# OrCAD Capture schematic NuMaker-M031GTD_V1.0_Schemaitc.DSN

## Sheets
1 Nu-Link2-Me: size A3; title: Nu-Link2-Me; rev: 1.0; company: WHChiu; note: Nu-Link2-Me
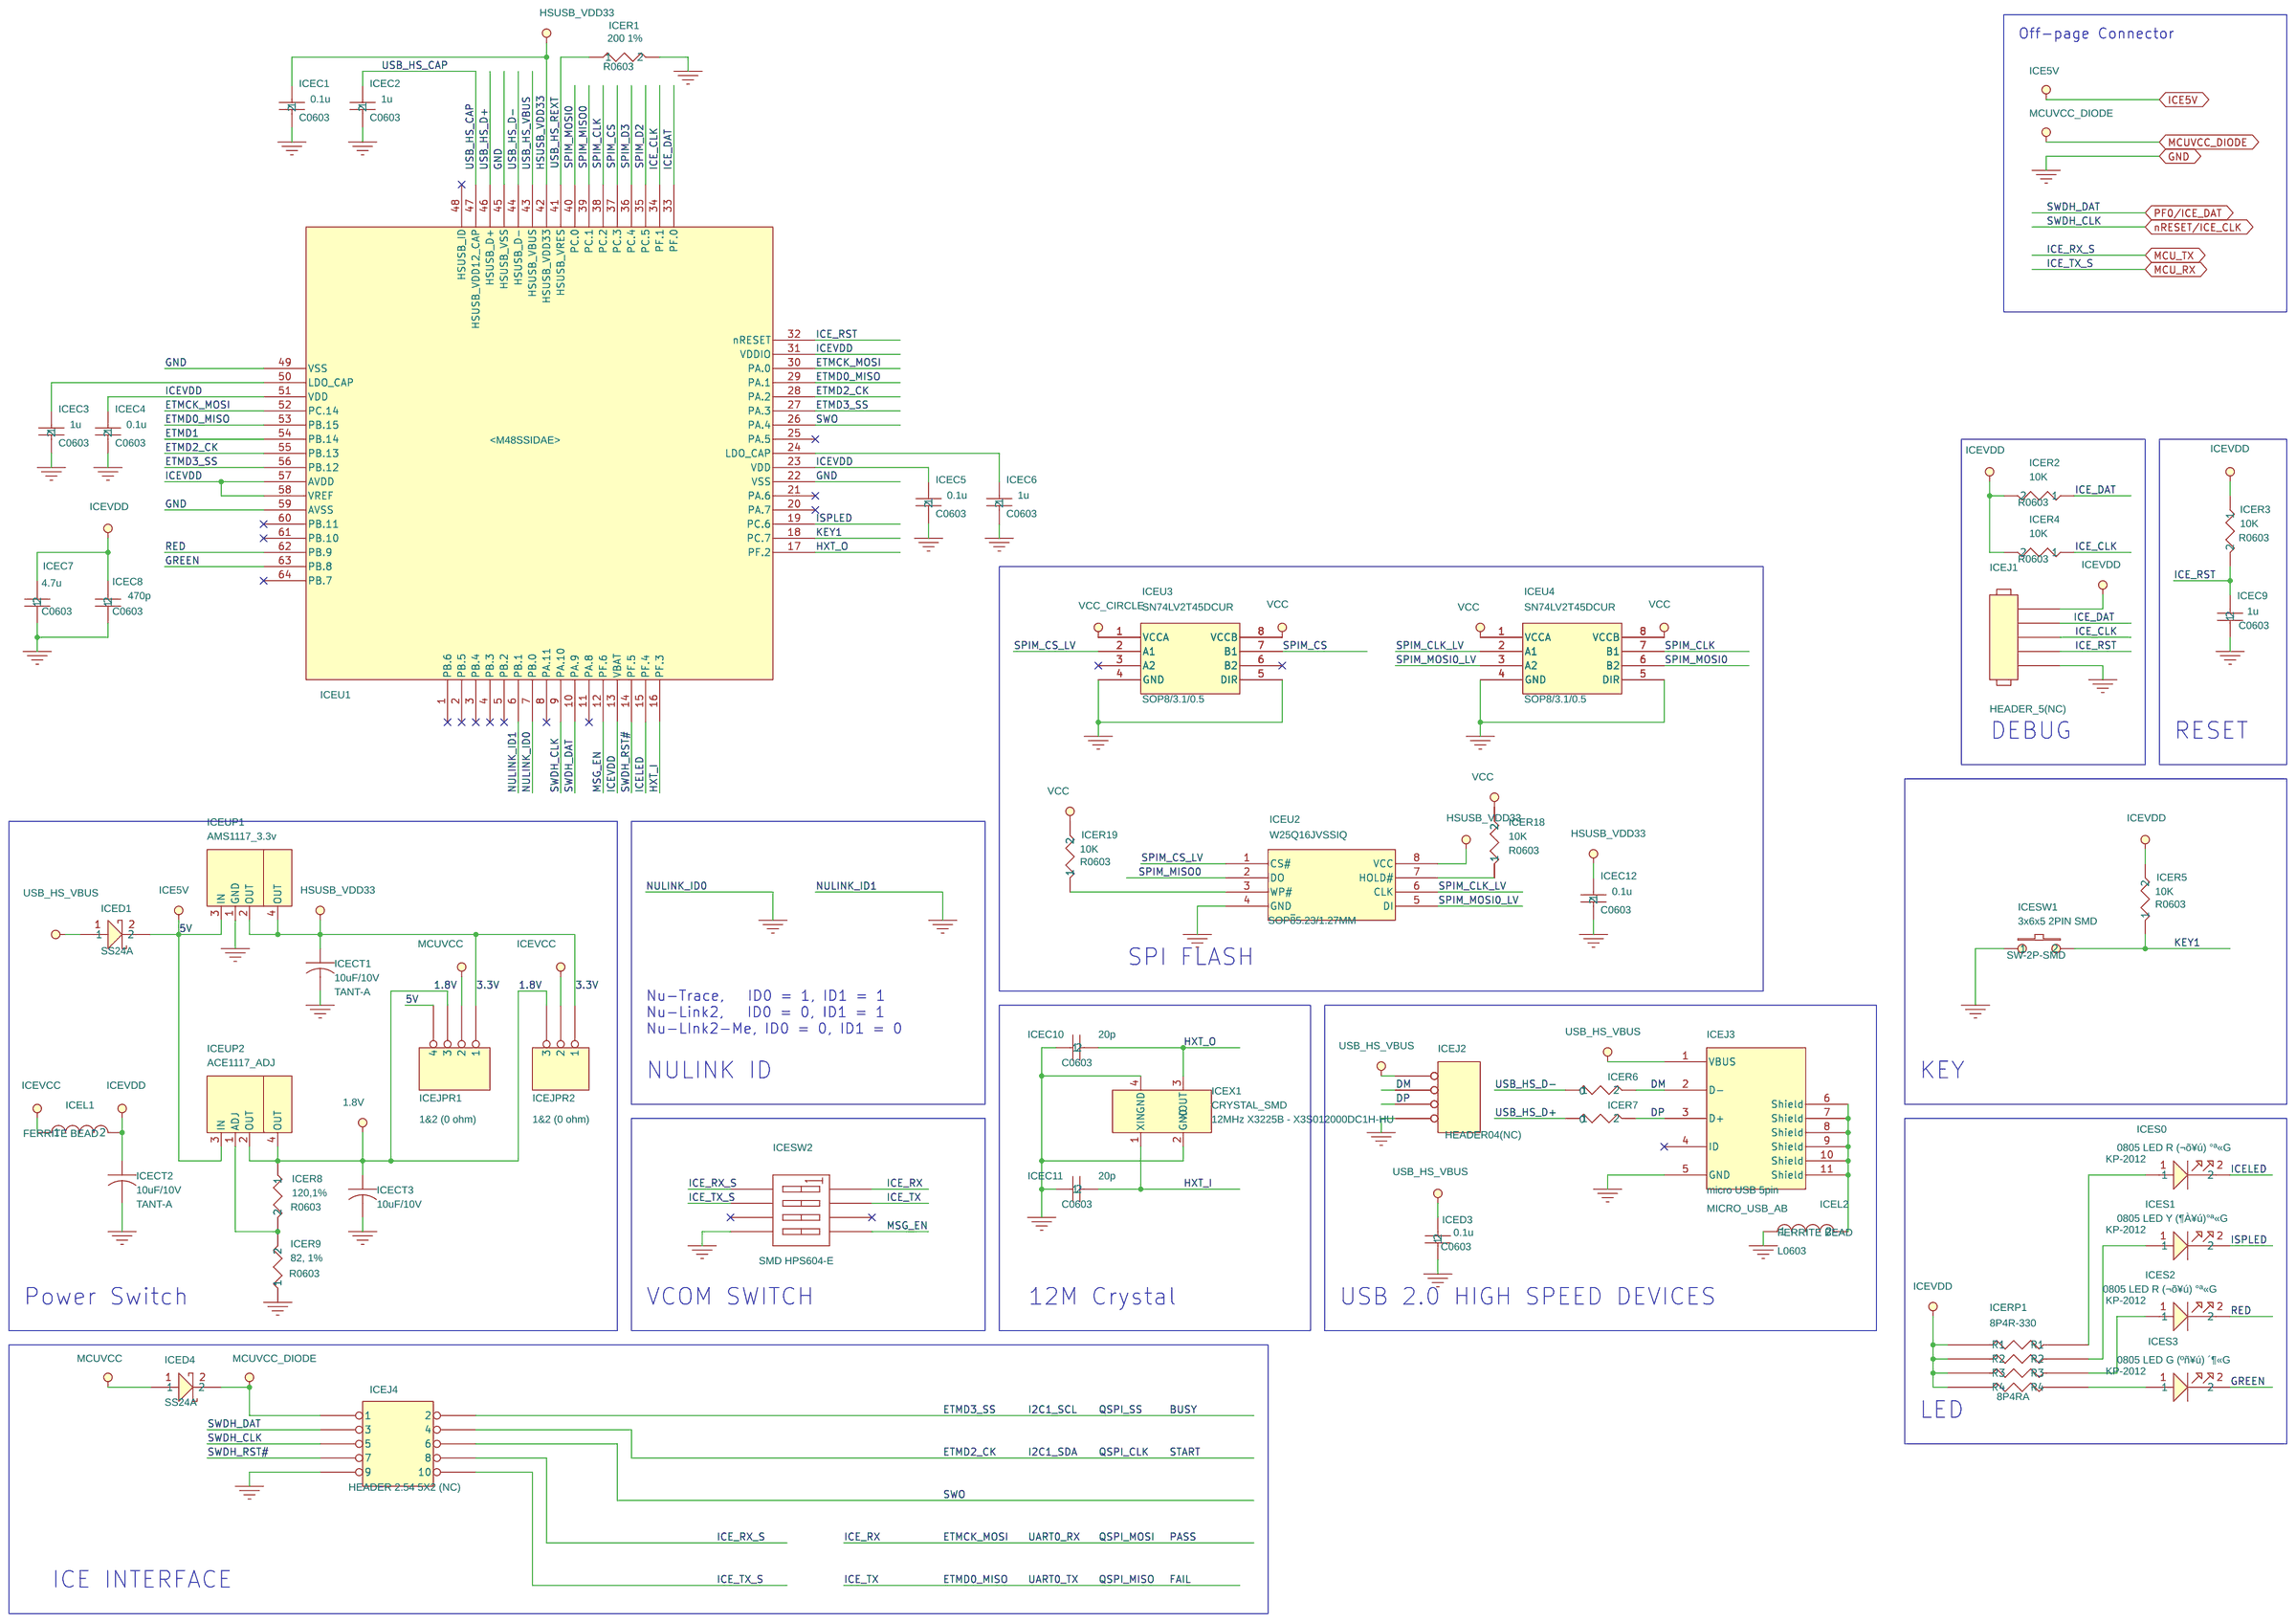
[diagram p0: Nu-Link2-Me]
2 M031G: size B; title: M031GTD2AE; rev: v1.1; note: NuMaker-M031G
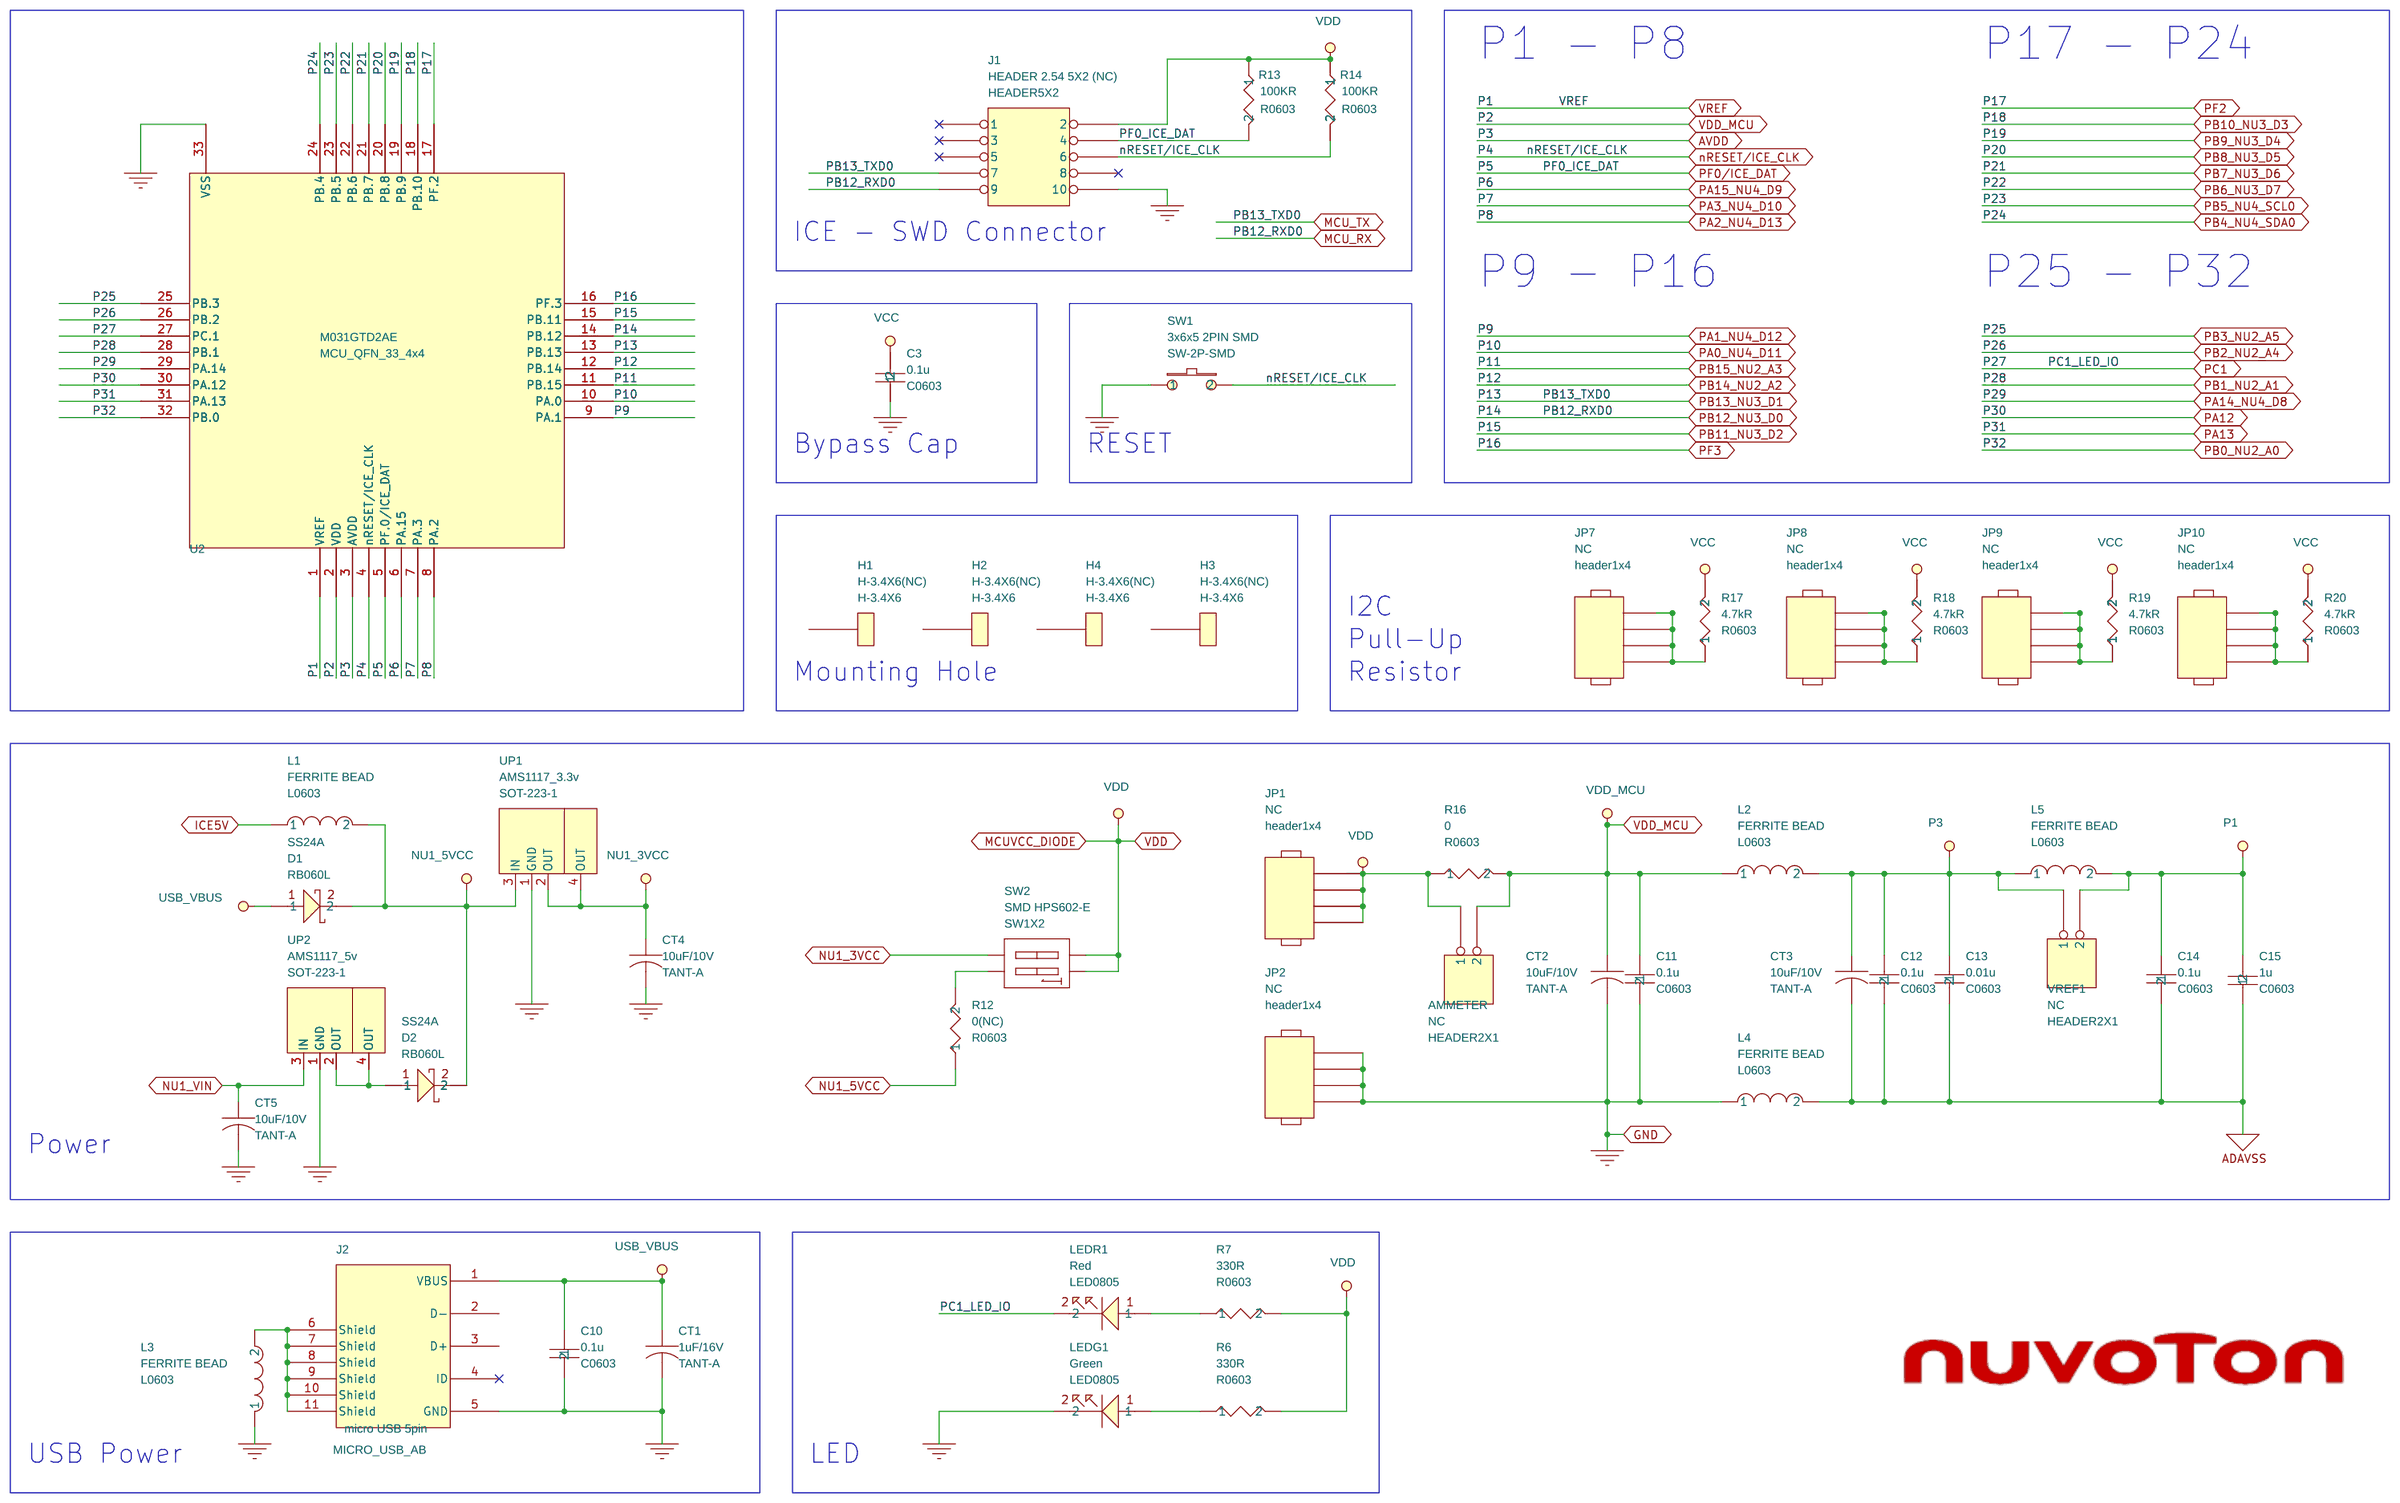
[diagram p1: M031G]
3 Ext. Connector: size A; title: Ext. Connector; rev: v1.1; note: NuMaker-M031G
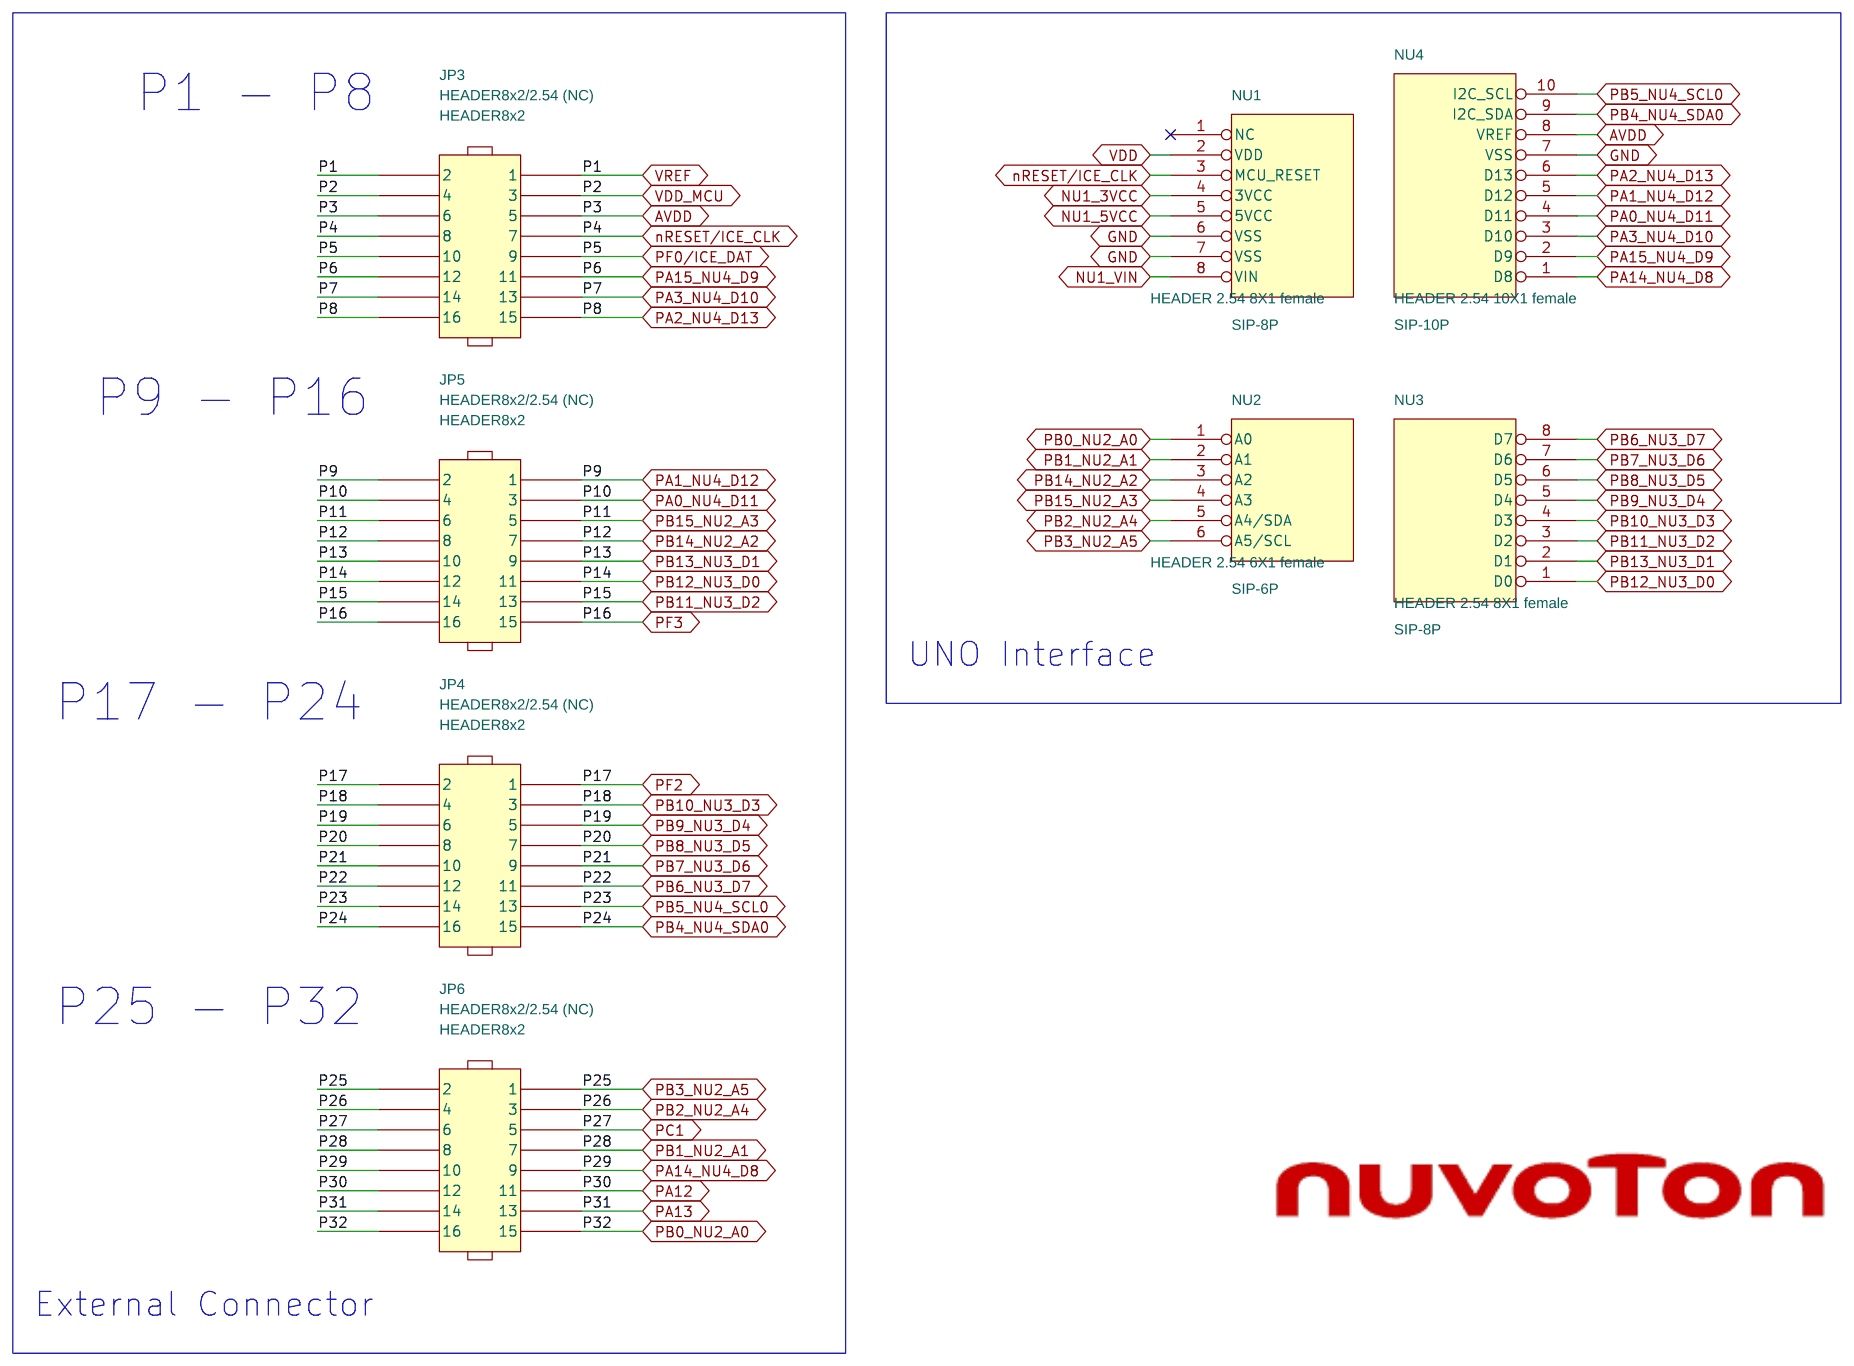
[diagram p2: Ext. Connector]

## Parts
sheet Ext. Connector
JP3  HEADER8x2/2.54 (NC)  [HEADER8x2]
JP4  HEADER8x2/2.54 (NC)  [HEADER8x2]
JP5  HEADER8x2/2.54 (NC)  [HEADER8x2]
JP6  HEADER8x2/2.54 (NC)  [HEADER8x2]
NU1  HEADER 2.54 8X1 female  [SIP-8P]
NU2  HEADER 2.54 6X1 female  [SIP-6P]
NU3  HEADER 2.54 8X1 female  [SIP-8P]
NU4  HEADER 2.54 10X1 female  [SIP-10P]
sheet M031G
AMMETER  NC  [HEADER2X1]
C3  0.1u  [C0603]
C10  0.1u  [C0603]
C11  0.1u  [C0603]
C12  0.1u  [C0603]
C13  0.01u  [C0603]
C14  0.1u  [C0603]
C15  1u  [C0603]
CT1  1uF/16V  [TANT-A]
CT2  10uF/10V  [TANT-A]
CT3  10uF/10V  [TANT-A]
CT4  10uF/10V  [TANT-A]
CT5  10uF/10V  [TANT-A]
D1  SS24A  [RB060L]
D2  SS24A  [RB060L]
H1  H-3.4X6(NC)  [H-3.4X6]
H2  H-3.4X6(NC)  [H-3.4X6]
H3  H-3.4X6(NC)  [H-3.4X6]
H4  H-3.4X6(NC)  [H-3.4X6]
J1  HEADER 2.54 5X2 (NC)  [HEADER5X2]
J2  micro USB 5pin  [MICRO_USB_AB]
JP1  NC  [header1x4]
JP2  NC  [header1x4]
JP7  NC  [header1x4]
JP8  NC  [header1x4]
JP9  NC  [header1x4]
JP10  NC  [header1x4]
L1  FERRITE BEAD  [L0603]
L2  FERRITE BEAD  [L0603]
L3  FERRITE BEAD  [L0603]
L4  FERRITE BEAD  [L0603]
L5  FERRITE BEAD  [L0603]
LEDG1  Green  [LED0805]
LEDR1  Red  [LED0805]
R6  330R  [R0603]
R7  330R  [R0603]
R12  0(NC)  [R0603]
R13  100KR  [R0603]
R14  100KR  [R0603]
R16  0  [R0603]
R17  4.7kR  [R0603]
R18  4.7kR  [R0603]
R19  4.7kR  [R0603]
R20  4.7kR  [R0603]
SW1  3x6x5 2PIN SMD  [SW-2P-SMD]
SW2  SMD HPS602-E  [SW1X2]
U2  M031TC1AE  [MCU_QFN_33_4x4]
UP1  AMS1117_3.3v  [SOT-223-1]
UP2  AMS1117_5v  [SOT-223-1]
VREF1  NC  [HEADER2X1]
sheet Nu-Link2-Me
ICEC1  0.1u  [C0603]
ICEC2  1u  [C0603]
ICEC3  1u  [C0603]
ICEC4  0.1u  [C0603]
ICEC5  0.1u  [C0603]
ICEC6  1u  [C0603]
ICEC7  4.7u  [C0603]
ICEC8  470p  [C0603]
ICEC9  1u  [C0603]
ICEC10  20p  [C0603]
ICEC11  20p  [C0603]
ICEC12  0.1u  [C0603]
ICECT1  10uF/10V  [TANT-A]
ICECT2  10uF/10V  [TANT-A]
ICECT3  10uF/10V  [TANT-A]
ICED1  SS24A  [RB060L]
ICED3  0.1u  [C0603]
ICED4  SS24A  [RB060L]
ICEJ1  HEADER_5(NC)  [HEADER5X1]
ICEJ2  HEADER04(NC)  [HEADER04]
ICEJ3  micro USB 5pin  [MICRO_USB_AB]
ICEJ4  HEADER 2.54 5X2 (NC)  [HEADER5X2]
ICEJPR1  1&2 (0 ohm)  [R0603X3]
ICEJPR2  1&2 (0 ohm)  [R0603X2]
ICEL1  FERRITE BEAD  [L0603]
ICEL2  FERRITE BEAD  [L0603]
ICER1  200 1%  [R0603]
ICER2  10K  [R0603]
ICER3  10K  [R0603]
ICER4  10K  [R0603]
ICER5  10K  [R0603]
ICER6  0  [R0603]
ICER7  0  [R0603]
ICER8  120,1%  [R0603]
ICER9  82, 1%  [R0603]
ICER18  10K  [R0603]
ICER19  10K  [R0603]
ICERP1  8P4R-330  [8P4RA]
ICES0  0805 LED R (¬õ¥ú) °ª«G  [KP-2012]
ICES1  0805 LED Y (¶À¥ú)°ª«G  [KP-2012]
ICES2  0805 LED R (¬õ¥ú) °ª«G  [KP-2012]
ICES3  0805 LED G (ºñ¥ú) ´¶«G  [KP-2012]
ICESW1  3x6x5 2PIN SMD  [SW-2P-SMD]
ICESW2  SMD HPS604-E  [SW1X4]
ICEU1  M48SSIDAE  [LQFP64_7x7_M48SSIDAE]
ICEU2  W25Q16JVSSIQ  [SOP8\5.23/1.27MM]
ICEU3  SN74LV2T45DCUR  [SOP8/3.1/0.5]
ICEU4  SN74LV2T45DCUR  [SOP8/3.1/0.5]
ICEUP1  AMS1117_3.3v  [SOT-223-1]
ICEUP2  ACE1117_ADJ  [SOT-223-1]
ICEX1  12MHz X3225B - X3S012000DC1H-HU  [CRYSTAL_SMD]

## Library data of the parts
JP3 = HEADER_8X2_3
JP4 = HEADER_8X2_1
JP5 = HEADER_8X2
JP6 = HEADER_8X2_2
NU1 = POWER_CONNECT_0
NU2 = ADC_CONNECT_0
NU3 = PWM0_CONNECT_0
NU4 = PWM1_CONNECT_1
AMMETER = HEADER_2_1
C3 ICED3 = CAP-C_1: Package: 0603; element_no: C0004
C10 = C_0.1u_3: element_no: C0004
C11 = C_0.1u: element_no: C0004
C12 = C_0.1u_1: element_no: C0004
C13 = C_0.1u_4: element_no: C0003
C14 = C_0.1u_2: element_no: C0004
C15 = CAP-C: Package: 0603; element_no: C0006
CT1 = C_1uF_16V
CT2-CT5 ICECT1-ICECT3 = C_10uF_10V
D1 ICED1 = D_SS24A
D2 ICED4 = D_SS24A_1
H1-H4 = TEST_POINT
ICEJ4 J1 = HEADER_5X2
ICEJ3 J2 = micro_USB_5pin_0
JP1 JP2 JP7-JP10 = HEADER_4
L1 = FERRITE_BEAD_4
L2 = FERRITE_BEAD_2
L3 = FERRITE_BEAD_3
ICEL2 L4 = FERRITE_BEAD_1
ICEL1 L5 = FERRITE_BEAD
LEDG1 = LED_0_1: Package: KP-2012; Vendor: Kingbright
LEDR1 = LED_0: Package: KP-2012; Vendor: Kingbright
ICER18 R6 = R_0_6: Package: 0603
ICER2 R7 = R_0: Package: 0603
R12 = R_0_5
ICER3 R13 = R_0_4: Package: 0603
ICER4 R14 = R_0_7: Package: 0603
R16 = R_0_9
R17 = R_0_1
R18 = R_0_2
R19 = R_0_3
R20 = R_0_8
ICESW1 SW1 = SW_PUSHBUTTON_0
SW2 = SW_DIP-4_2
U2 = M031TC1AE_1: M031TC1AE: M031GTD2AE
ICEUP1 UP1 UP2 = TO-247_Regulator_10
VREF1 = HEADER_2
ICEC1 = CAP-C_9: Package: 0603; element_no: C0004
ICEC2 = CAP-C_10: Package: 0603; element_no: C0006
ICEC3 = CAP-C_11: Package: 0603; element_no: C0006
ICEC4 = CAP-C_2: Package: 0603; element_no: C0004
ICEC5 = CAP-C_4: Package: 0603; element_no: C0004
ICEC6 = CAP-C_5: Package: 0603; element_no: C0006
ICEC7 = CAP-C: Package: 0603
ICEC8 = CAP-C_6: Package: 0603
ICEC9 = CAP-C_7: Package: 0603; element_no: C0006
ICEC10 = CAP-C_3: Package: 0603
ICEC11 = CAP-C_12: Package: 0603
ICEC12 = CAP-C_8: Package: 0603; element_no: C0004
ICEJ1 = HEADER_5_v2
ICEJ2 = HEADER_4_v2
ICEJPR1 = HEADER_3_0
ICEJPR2 = HEADER_3
ICER1 = R_0_5: Package: 0603
ICER5 = R_0_2: Package: 0603
ICER6 = R_33
ICER7 = R_33_1
ICER8 = R_0_3: Package: 0603
ICER9 = R_0_8: Package: 0603
ICER19 = R_0_1: Package: 0603
ICERP1 = R-PACK8_0
ICES0 = LED_0_3: Vendor: Kingbright
ICES1 = LED_0_1: Vendor: Kingbright
ICES2 = LED_0: Vendor: Kingbright
ICES3 = LED_0_2: Vendor: Kingbright
ICESW2 = SW_DIP-4_SM
ICEU1 = M487SIDAE_0: M487SIDAE: <M48SSIDAE>
ICEU2 = W25P10_20_40_SOIC_0: Package: SOP8; Vendor: WINBOND
ICEU3 ICEU4 = SN74LV2T45
ICEUP2 = TO-247_Regulator_0
ICEX1 = Crystal_SMD_1

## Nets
1.8V: ICECT3.1 ICEJPR1.3 ICEJPR2.3 ICER8.1 ICEUP2.2(OUT) ICEUP2.4(OUT)
3.3V: ICEC1.1 ICEC12.1 ICECT1.1 ICEJPR1.1 ICEJPR2.1 ICER18.2 ICER19.2 ICEU1.42(HSUSB_VDD33) ICEU2.8(VCC) ICEU3.1(VCCA) ICEU4.1(VCCA) ICEUP1.2(OUT) ICEUP1.4(OUT)
AVDD: C12.1 C13.1 CT3.1 JP3.5 JP3.6 L2.2 L5.1 NU4.8(VREF) U2.3(AVDD) VREF1.1
AVSS: C12.2 C13.2 C14.2 C15.1 CT3.2 L4.2
GND: C3.1 C10.2 C11.2 CT1.2 CT2.2 CT4.2 CT5.2 ICEC1.2 ICEC2.2 ICEC3.2 ICEC4.2 ICEC5.2 ICEC6.2 ICEC7.1 ICEC8.1 ICEC9.1 ICEC10.1 ICEC11.1 ICEC12.2 ICECT1.2 ICECT2.2 ICECT3.2 ICED3.1 ICEJ1.5 ICEJ2.4 ICEJ3.5(GND) ICEJ4.9 ICEL2.1 ICER1.2 ICER9.1 ICESW1.1 ICESW2.4(A4) ICEU1.6(PB.1) ICEU1.7(PB.0) ICEU1.22(VSS) ICEU1.45(HSUSB_VSS) ICEU1.49(VSS) ICEU1.59(AVSS) ICEU2.4(GND) ICEU3.4(GND) ICEU3.5(DIR) ICEU4.4(GND) ICEU4.5(DIR) ICEUP1.1(GND) ICEX1.2(GND) ICEX1.4(GND) J1.10 J2.5(GND) JP2.1 JP2.2 JP2.3 JP2.4 L3.1 L4.1 LEDG1.2 NU1.6(VSS) NU1.7(VSS) NU4.7(VSS) SW1.1 U2.33(VSS) UP1.1(GND) UP2.1(GND)
VDD_MCU: AMMETER.2 C3.2 C11.1 CT2.1 JP3.3 JP3.4 L2.1 R16.2 U2.2(VDD)
BUSY: ICEJ4.2 ICEU1.27(PA.3) ICEU1.56(PB.12)
DM: ICEJ2.2 ICEJ3.2(D-) ICER6.2
DP: ICEJ2.3 ICEJ3.3(D+) ICER7.2
ETMD1: ICEU1.54(PB.14)
ETMD2_CK: ICEJ4.4 ICEU1.28(PA.2) ICEU1.55(PB.13)
GREEN: ICES3.2 ICEU1.63(PB.8)
HXT_I: ICEC11.2 ICEU1.16(PF.3) ICEX1.1(XIN)
HXT_O: ICEC10.2 ICEU1.17(PF.2) ICEX1.3(XOUT)
ICE5V: ICED1.2 ICEJPR1.4 ICEUP1.3(IN) ICEUP2.3(IN) L1.1
ICE_CLK: ICEJ1.3 ICER4.1 ICEU1.34(PF.1)
ICE_DAT: ICEJ1.2 ICER2.1 ICEU1.33(PF.0)
ICE_RST: ICEC9.2 ICEJ1.4 ICER3.2 ICEU1.32(nRESET)
ICE_RX: ICESW2.8(B1) ICEU1.30(PA.0) ICEU1.52(PC.14)
ICE_TX: ICESW2.7(B2) ICEU1.29(PA.1) ICEU1.53(PB.15)
ICELED: ICES0.2 ICEU1.15(PF.4)
ICEVCC: ICEJPR2.2 ICEL1.1
ICEVDD: ICEC4.1 ICEC5.1 ICEC7.2 ICEC8.2 ICECT2.1 ICEJ1.1 ICEL1.2 ICER2.2 ICER3.1 ICER4.2 ICER5.2 ICERP1.1(R1) ICERP1.3(R2) ICERP1.5(R3) ICERP1.7(R4) ICEU1.13(VBAT) ICEU1.23(VDD) ICEU1.31(VDDIO) ICEU1.51(VDD) ICEU1.57(AVDD) ICEU1.58(VREF) ICEU3.8(VCCB) ICEU4.8(VCCB)
ISPLED: ICES1.2 ICEU1.19(PC.6)
KEY1: ICER5.1 ICESW1.2 ICEU1.18(PC.7)
MCU_RX: ICEJ4.10 ICESW2.2(A2) J1.9 JP5.11 JP5.12 NU3.1(D0) U2.14(PB.12)
MCU_TX: ICEJ4.8 ICESW2.1(A1) J1.7 JP5.9 JP5.10 NU3.2(D1) U2.13(PB.13)
MCUVCC: ICED4.1 ICEJPR1.2
MCUVCC_DIODE: AMMETER.1 ICED4.2 ICEJ4.1 J1.2 JP1.1 JP1.2 JP1.3 JP1.4 NU1.2(VDD) R6.2 R7.2 R13.1 R14.1 R16.1 R17.2 R18.2 R19.2 R20.2 SW2.3(B1) SW2.4(B2)
MSG_EN: ICESW2.5(B4) ICEU1.12(PF.6)
nRESET/ICE_CLK: ICEJ4.5 ICEU1.9(PA.10) J1.6 JP3.7 JP3.8 NU1.3(MCU_RESET) R14.2 SW1.2 U2.4(nRESET/ICE_CLK)
NU1_3VCC: CT4.1 NU1.4(3VCC) SW2.2(A2) UP1.2(OUT) UP1.4(OUT)
NU1_5VCC: D1.2 D2.2 L1.2 NU1.5(5VCC) R12.1 UP1.3(IN)
NU1_VIN: CT5.1 NU1.8(VIN) UP2.3(IN)
PA0_NU4_D11: JP5.3 JP5.4 NU4.4(D11) U2.10(PA.0)
PA1_NU4_D12: JP5.1 JP5.2 NU4.5(D12) U2.9(PA.1)
PA2_NU4_D13: JP3.15 JP3.16 NU4.6(D13) U2.8(PA.2)
PA3_NU4_D10: JP3.13 JP3.14 NU4.3(D10) U2.7(PA.3)
PA12: JP6.11 JP6.12 U2.30(PA.12)
PA13: JP6.13 JP6.14 U2.31(PA.13)
PA14_NU4_D8: JP6.9 JP6.10 NU4.1(D8) U2.29(PA.14)
PA15_NU4_D9: JP3.11 JP3.12 NU4.2(D9) U2.6(PA.15)
PB0_NU2_A0: JP6.15 JP6.16 NU2.1(A0) U2.32(PB.0)
PB1_NU2_A1: JP6.7 JP6.8 NU2.2(A1) U2.28(PB.1)
PB2_NU2_A4: JP6.3 JP6.4 NU2.5(A4/SDA) U2.26(PB.2)
PB3_NU2_A5: JP6.1 JP6.2 NU2.6(A5/SCL) U2.25(PB.3)
PB4_NU4_SDA0: JP4.15 JP4.16 NU4.9(I2C_SDA) U2.24(PB.4)
PB5_NU4_SCL0: JP4.13 JP4.14 NU4.10(I2C_SCL) U2.23(PB.5)
PB6_NU3_D7: JP4.11 JP4.12 NU3.8(D7) U2.22(PB.6)
PB7_NU3_D6: JP4.9 JP4.10 NU3.7(D6) U2.21(PB.7)
PB8_NU3_D5: JP4.7 JP4.8 NU3.6(D5) U2.20(PB.8)
PB9_NU3_D4: JP4.5 JP4.6 NU3.5(D4) U2.19(PB.9)
PB10_NU3_D3: JP4.3 JP4.4 NU3.4(D3) U2.18(PB.10)
PB11_NU3_D2: JP5.13 JP5.14 NU3.3(D2) U2.15(PB.11)
PB14_NU2_A2: JP5.7 JP5.8 NU2.3(A2) U2.12(PB.14)
PB15_NU2_A3: JP5.5 JP5.6 NU2.4(A3) U2.11(PB.15)
PC1: JP6.5 JP6.6 LEDR1.2 U2.27(PC.1)
PF0/ICE_DAT: ICEJ4.3 ICEU1.10(PA.9) J1.4 JP3.9 JP3.10 R13.2 U2.5(PF.0/ICE_DAT)
PF2: JP4.1 JP4.2 U2.17(PF.2)
PF3: JP5.15 JP5.16 U2.16(PF.3)
RED: ICES2.2 ICEU1.62(PB.9)
SPIM_CLK: ICEU1.38(PC.2) ICEU4.7(B1)
SPIM_CLK_LV: ICEU2.6(CLK) ICEU4.2(A1)
SPIM_CS: ICEU1.37(PC.3) ICEU3.7(B1)
SPIM_CS_LV: ICEU2.1(CS#) ICEU3.2(A1)
SPIM_D2: ICEU1.35(PC.5)
SPIM_D3: ICEU1.36(PC.4)
SPIM_MISO0: ICEU1.39(PC.1) ICEU2.2(DO)
SPIM_MOSI0: ICEU1.40(PC.0) ICEU4.6(B2)
SPIM_MOSI0_LV: ICEU2.5(DI) ICEU4.3(A2)
SWDH_RST#: ICEJ4.7 ICEU1.14(PF.5)
SWO: ICEJ4.6 ICEU1.26(PA.4)
USB_HS_CAP: ICEC2.1 ICEU1.47(HSUSB_VDD12_CAP)
USB_HS_D+: ICER7.1 ICEU1.46(HSUSB_D+)
USB_HS_D-: ICER6.1 ICEU1.44(HSUSB_D-)
USB_HS_REXT: ICER1.1 ICEU1.41(HSUSB_VRES)
USB_HS_VBUS: ICED1.1 ICED3.2 ICEJ2.1 ICEJ3.1(VBUS) ICEU1.43(HSUSB_VBUS)
USB_VBUS: C10.1 CT1.1 D1.1 J2.1(VBUS)
VREF: C14.1 C15.2 JP3.1 JP3.2 L5.2 U2.1(VREF) VREF1.2
N16840819: ICEC6.1 ICEU1.24(LDO_CAP)
N16840960: ICEC3.1 ICEU1.50(LDO_CAP)
N17019924: ICER8.2 ICER9.2 ICEUP2.1(ADJ)
N17029977: ICERP1.8(R4) ICES3.1
N17029979: ICERP1.6(R3) ICES2.1
N17030004: ICERP1.4(R2) ICES1.1
N17030010: ICERP1.2(R1) ICES0.1
N17042369: ICEJ3.6(Shield) ICEJ3.7(Shield) ICEJ3.8(Shield) ICEJ3.9(Shield) ICEJ3.10(Shield) ICEJ3.11(Shield) ICEL2.2
N17110356: J2.6(Shield) J2.7(Shield) J2.8(Shield) J2.9(Shield) J2.10(Shield) J2.11(Shield) L3.2
N17155328: ICER18.1 ICEU2.7(HOLD#)
N17155343: ICER19.1 ICEU2.3(WP#)
N17167442: D2.1 UP2.2(OUT) UP2.4(OUT)
N17227520: LEDR1.1 R7.1
N17227603: LEDG1.1 R6.1
N17246180: R12.2 SW2.1(A1)
N17256935: JP7.1 JP7.2 JP7.3 JP7.4 R17.1
N17258939: JP8.1 JP8.2 JP8.3 JP8.4 R18.1
N17259043: JP9.1 JP9.2 JP9.3 JP9.4 R19.1
N17259286: JP10.1 JP10.2 JP10.3 JP10.4 R20.1

Not connected (* = marked no-connect by the designer): H1 1; H2 1; H3 1; H4 1; ICEJ3 4(ID)*; ICESW2 3(A3)* 6(B3)*; ICEU1 1(PB.6)* 2(PB.5)* 3(PB.4)* 4(PB.3)* 5(PB.2)* 8(PA.11)* 11(PA.8)* 20(PA.7)* 21(PA.6)* 25(PA.5)* 48(HSUSB_ID)* 60(PB.11)* 61(PB.10)* 64(PB.7)*; ICEU3 3(A2)* 6(B2)*; J1 1* 3* 5* 8*; J2 2(D-) 3(D+) 4(ID)*; NU1 1(NC)*

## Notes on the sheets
sheet 1
- Off-page Connector
- DEBUG
- RESET
- SPI FLASH
- Nu-Trace,   ID0 = 1, ID1 = 1
  Nu-Link2,   ID0 = 0, ID1 = 1
  Nu-LInk2-Me, ID0 = 0, ID1 = 0
- NULINK ID
- KEY
- Power Switch
- VCOM SWITCH
- 12M Crystal
- USB 2.0 HIGH SPEED DEVICES
- LED
- ICE INTERFACE
sheet 2
- P1 - P8
- P17 - P24
- ICE - SWD Connector
- P9 - P16
- P25 - P32
- Bypass Cap
- RESET
- I2C
- Pull-Up
- Mounting Hole
- Resistor
- Power
- USB Power
- LED
sheet 3
- P1 - P8
- P9 - P16
- UNO Interface
- P17 - P24
- P25 - P32
- External Connector
